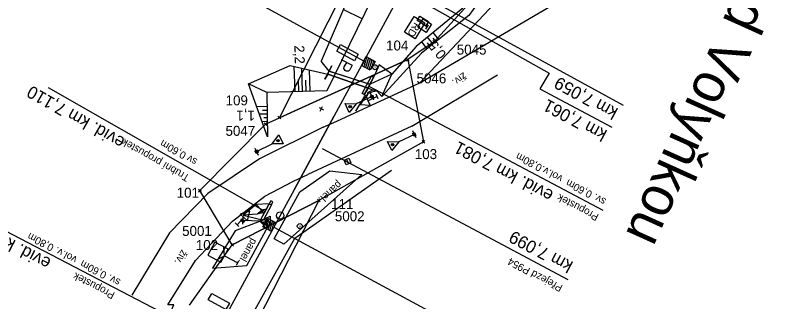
# Model space of a CAD drawing. Extents: x -795094 to -794639, y -1135368 to -1134681.
# Drawn here: x -794952.7 to -794797.7, y -1135065.2 to -1135007.8 of the extents above; entities that cross this region are included whole.
import ezdxf

# ---------------------------------------------------------------- set-up
doc = ezdxf.new("R2010")
doc.units = 0
for name, color, linetype in [('0381KM005-009P - Vrstva 1', 7, 'Continuous'), ('0381KM005-009P - Vrstva 12', 7, 'Continuous'), ('0381KM005-009P - Vrstva 13', 7, 'Continuous'), ('0381KM005-009P - Vrstva 16', 7, 'Continuous'), ('0381KM005-009P - Vrstva 17', 7, 'Continuous'), ('0381KM005-009P - Vrstva 19', 7, 'Continuous'), ('0381KM005-009P - Vrstva 2', 7, 'Continuous'), ('0381KM005-009P - Vrstva 23', 7, 'Continuous'), ('0381KM005-009P - Vrstva 25', 7, 'Continuous'), ('0381KM005-009P - Vrstva 28', 7, 'Continuous'), ('0381KM005-009P - Vrstva 3', 7, 'Continuous'), ('0381KM005-009P - Vrstva 33', 7, 'Continuous'), ('0381KM005-009P - Vrstva 4', 7, 'Continuous'), ('0381KM005-009P - Vrstva 43', 7, 'Continuous'), ('0381KM005-009P - Vrstva 48', 7, 'Continuous'), ('0381KM005-009P - Vrstva 49', 7, 'Continuous'), ('0381KM005-009P - Vrstva 51', 7, 'Continuous'), ('0381KM005-009P - Vrstva 7', 7, 'Continuous'), ('szdc - hran DP', 7, 'Continuous'), ('szdc - szdc_cislo', 7, 'Continuous'), ('szdc - szdc_krizek', 7, 'Continuous'), ('TZ - TZ_cislo', 7, 'Continuous'), ('TZ - TZ_krizek', 7, 'Continuous'), ('TZ - TZ_ostat', 7, 'Continuous')]:
    doc.layers.add(name, color=color, linetype=linetype)

msp = doc.modelspace()

# ---------------------------------------------------------------- linework, layer by layer
at = {"layer": '0381KM005-009P - Vrstva 1'}
for points in [[(-794874.77, -1135001.82), (-794875.27, -1135002.76), (-794882.94, -1135016.95), (-794888.88, -1135027.93)], [(-794888.88, -1135027.93), (-794896.92, -1135042.83), (-794900.95, -1135050.28), (-794913.19, -1135072.81), (-794931.08, -1135105.64), (-794935.69, -1135114.26)]]:
    msp.add_lwpolyline(points, dxfattribs=at)
at = {"layer": '0381KM005-009P - Vrstva 12'}
for p, q in [((-794881.46, -1135024.4), (-794881.59, -1135023.95)), ((-794881.14, -1135023.79), (-794881.13, -1135023.79)), ((-794872.92, -1135032.06), (-794872.91, -1135032.06)), ((-794872.5, -1135031.85), (-794872.5, -1135031.85)), ((-794907.35, -1135048.62), (-794907.35, -1135048.62)), ((-794907.6, -1135048.97), (-794907.58, -1135048.95)), ((-794907.09, -1135049.34), (-794907.1, -1135049.36)), ((-794906.84, -1135049.01), (-794906.84, -1135049.01))]:
    msp.add_line(p, q, dxfattribs=at)
for points in [[(-794881.59, -1135023.95), (-794881.14, -1135023.79), (-794880.98, -1135024.24), (-794881.46, -1135024.39), (-794881.59, -1135023.95), (-794881.59, -1135023.95), (-794881.13, -1135023.79), (-794880.98, -1135024.24), (-794880.98, -1135024.24)], [(-794880.98, -1135024.24), (-794881.46, -1135024.4), (-794881.46, -1135024.39)], [(-794873.17, -1135031.49), (-794872.8, -1135031.31), (-794872.5, -1135031.85), (-794872.92, -1135032.06), (-794873.17, -1135031.49), (-794873.17, -1135031.5), (-794872.8, -1135031.31), (-794872.5, -1135031.85), (-794872.91, -1135032.06), (-794873.17, -1135031.5)], [(-794904.34, -1135035.49), (-794904.78, -1135035.05), (-794904.46, -1135034.75), (-794904.04, -1135035.23), (-794904.34, -1135035.49)], [(-794907.6, -1135048.97), (-794907.35, -1135048.62), (-794906.84, -1135049.01), (-794907.09, -1135049.34), (-794907.6, -1135048.97)], [(-794907.58, -1135048.95), (-794907.35, -1135048.62), (-794906.84, -1135049.01), (-794907.1, -1135049.36), (-794907.58, -1135048.95)]]:
    msp.add_lwpolyline(points, dxfattribs=at)
at = {"layer": '0381KM005-009P - Vrstva 13'}
msp.add_line((-794884.56, -1135027.04), (-794882.71, -1135024.01), dxfattribs=at)
for points in [[(-794882.37, -1135024.01), (-794882.1, -1135023.18), (-794881.15, -1135022.72), (-794880.34, -1135022.96)], [(-794882.37, -1135024.01), (-794881.98, -1135023.4), (-794881.04, -1135023.04), (-794880.34, -1135022.96)]]:
    msp.add_lwpolyline(points, dxfattribs=at)
at = {"layer": '0381KM005-009P - Vrstva 16'}
for points in [[(-794898.94, -1135053.67), (-794900.91, -1135052.62), (-794895.75, -1135043.22), (-794889.78, -1135038.98), (-794883.31, -1135039.73)], [(-794906.39, -1135057.97), (-794902.12, -1135050.06), (-794903.85, -1135049.17), (-794908.68, -1135051.01), (-794913.25, -1135058.52)]]:
    msp.add_lwpolyline(points, close=True, dxfattribs=at)
at = {"layer": '0381KM005-009P - Vrstva 17'}
msp.add_lwpolyline([(-794906.48, -1135078.85), (-794910.34, -1135076.94), (-794896.76, -1135052.47), (-794877.42, -1135038.88)], dxfattribs=at)
at = {"layer": '0381KM005-009P - Vrstva 19'}
for p, q in [((-794889.88, -1135018.97), (-794881.68, -1135021.6)), ((-794881.72, -1135021.67), (-794889.88, -1135018.99)), ((-794882.1, -1135022.38), (-794890.17, -1135019.59)), ((-794890.16, -1135019.57), (-794882.1, -1135022.38)), ((-794880.99, -1135020.22), (-794880.96, -1135020.15)), ((-794902.71, -1135047.12), (-794946.12, -1135022.34)), ((-794881.93, -1135021.97), (-794835.06, -1135046.89)), ((-794901.41, -1135045.78), (-794901.14, -1135045.23)), ((-794903.29, -1135047.16), (-794904.32, -1135047.68)), ((-794916, -1135071.26), (-794961.47, -1135047.52))]:
    msp.add_line(p, q, dxfattribs=at)
for points in [[(-794890.17, -1135019.59), (-794890.74, -1135020.61), (-794889.35, -1135017.89), (-794889.88, -1135018.97)], [(-794890.17, -1135019.59), (-794890.16, -1135019.57), (-794889.88, -1135018.99), (-794889.88, -1135018.97)], [(-794881.43, -1135019.98), (-794880.96, -1135020.15), (-794881.68, -1135021.6), (-794881.72, -1135021.67), (-794882.1, -1135022.38), (-794882.1, -1135022.38), (-794882.86, -1135023.7)], [(-794903.57, -1135048.72), (-794902.85, -1135047.4), (-794902.85, -1135047.4), (-794902.44, -1135046.65), (-794902.44, -1135046.66), (-794901.89, -1135045.6)], [(-794901.14, -1135045.23), (-794901.54, -1135045.02), (-794901.89, -1135045.6)], [(-794903.11, -1135047.41), (-794904.32, -1135047.68), (-794903.41, -1135046.89)]]:
    msp.add_lwpolyline(points, dxfattribs=at)
for points in [[(-794881.43, -1135019.98), (-794880.99, -1135020.22), (-794882.86, -1135023.7), (-794883.29, -1135023.48)], [(-794903.13, -1135048.93), (-794903.57, -1135048.72), (-794901.89, -1135045.6), (-794901.41, -1135045.78)]]:
    msp.add_lwpolyline(points, close=True, dxfattribs=at)
msp.add_ellipse((-794903.26, -1135047.17), major_axis=(0.173, -0.304), ratio=0.062911, start_param=2.649673, end_param=6.913725, dxfattribs=at)
at = {"layer": '0381KM005-009P - Vrstva 2'}
msp.add_line((-794830.92, -1135025.88), (-794874.77, -1135001.82), dxfattribs=at)
at = {"layer": '0381KM005-009P - Vrstva 23'}
msp.add_lwpolyline([(-794874.82, -1135011.19), (-794872.86, -1135008.04), (-794870.71, -1135009.3), (-794872.68, -1135012.53)], close=True, dxfattribs=at)
at = {"layer": '0381KM005-009P - Vrstva 25'}
msp.add_lwpolyline([(-794870.01, -1135009), (-794870.52, -1135009.86), (-794872.24, -1135008.85), (-794871.74, -1135007.98), (-794870.01, -1135009)], dxfattribs=at)
at = {"layer": '0381KM005-009P - Vrstva 28'}
for p, q in [((-794880.68, -1135018.15), (-794880.73, -1135018.23)), ((-794902.92, -1135049.17), (-794902.97, -1135049.26))]:
    msp.add_line(p, q, dxfattribs=at)
for centre in [(-794880.7, -1135018.19), (-794902.95, -1135049.22)]:
    msp.add_circle(centre, 0.5, dxfattribs=at)
at = {"layer": '0381KM005-009P - Vrstva 3'}
for p, q in [((-794882.94, -1135016.95), (-794926.07, -1134993.29)), ((-794881.65, -1135018.78), (-794882.46, -1135016.07)), ((-794883.05, -1135018.03), (-794883.22, -1135017.47)), ((-794882.59, -1135018.28), (-794882.97, -1135017.01)), ((-794882.12, -1135018.53), (-794882.72, -1135016.54)), ((-794881.4, -1135018.32), (-794882, -1135016.33)), ((-794881.15, -1135017.85), (-794881.53, -1135016.58)), ((-794880.9, -1135017.38), (-794881.06, -1135016.83)), ((-794902.23, -1135048.45), (-794901.42, -1135051.16)), ((-794901.76, -1135048.7), (-794901.17, -1135050.69)), ((-794902.98, -1135049.84), (-794902.82, -1135050.4)), ((-794902.73, -1135049.38), (-794902.35, -1135050.65)), ((-794902.48, -1135048.91), (-794901.89, -1135050.9)), ((-794901.29, -1135048.95), (-794900.92, -1135050.23)), ((-794900.95, -1135050.28), (-794850.2, -1135077.72)), ((-794900.83, -1135049.21), (-794900.66, -1135049.76))]:
    msp.add_line(p, q, dxfattribs=at)
msp.add_lwpolyline([(-794875.27, -1135002.76), (-794845.8, -1135019.38), (-794847.67, -1135022.54), (-794833.28, -1135030.23)], dxfattribs=at)
for points in [[(-794883.41, -1135017.83), (-794882.46, -1135016.07), (-794880.7, -1135017.02), (-794881.65, -1135018.78)], [(-794900.47, -1135049.4), (-794901.42, -1135051.16), (-794903.18, -1135050.2), (-794902.23, -1135048.45)]]:
    msp.add_lwpolyline(points, close=True, dxfattribs=at)
at = {"layer": '0381KM005-009P - Vrstva 33'}
for p, q in [((-794870.35, -1135010.12), (-794871.19, -1135009.59)), ((-794870.08, -1135009.7), (-794870.61, -1135010.55))]:
    msp.add_line(p, q, dxfattribs=at)
for points in [[(-794869.39, -1135009.54), (-794870.45, -1135011.24), (-794872.15, -1135010.18), (-794871.09, -1135008.48), (-794869.39, -1135009.54)], [(-794887.47, -1135016.62), (-794885.26, -1135017.81)], [(-794886.85, -1135018.14), (-794886.35, -1135017.22)], [(-794885.26, -1135017.81), (-794885.76, -1135018.73)], [(-794885.76, -1135018.73), (-794886, -1135018.96), (-794886.46, -1135018.96), (-794886.66, -1135018.86), (-794886.92, -1135018.46), (-794886.85, -1135018.14)]]:
    msp.add_lwpolyline(points, dxfattribs=at)
for points in [[(-794884.07, -1135015.58), (-794884.78, -1135016.89), (-794888.32, -1135014.98), (-794887.61, -1135013.67)], [(-794909.87, -1135065.52), (-794910.59, -1135066.82), (-794914.13, -1135064.9), (-794913.41, -1135063.59)]]:
    msp.add_lwpolyline(points, close=True, dxfattribs=at)
at = {"layer": '0381KM005-009P - Vrstva 4'}
for p, q in [((-794880.96, -1135024.79), (-794881.61, -1135023.37)), ((-794885.44, -1135026.22), (-794885.9, -1135026.04)), ((-794896.92, -1135042.83), (-794888.88, -1135027.93)), ((-794872.48, -1135032.38), (-794873.14, -1135030.97)), ((-794900.36, -1135032.84), (-794899.9, -1135033)), ((-794904.79, -1135034.42), (-794904.09, -1135035.82)), ((-794891.29, -1135034.51), (-794842.11, -1135060.79)), ((-794876.96, -1135033.83), (-794877.42, -1135033.66)), ((-794907.18, -1135048.11), (-794907.23, -1135049.66)), ((-794902.53, -1135048.84), (-794902.2, -1135049.2))]:
    msp.add_line(p, q, dxfattribs=at)
for points in [[(-794881.29, -1135024.08), (-794884.45, -1135025.53), (-794885.86, -1135027.27), (-794886.7, -1135025.45), (-794884.45, -1135025.53)], [(-794872.81, -1135031.68), (-794875.96, -1135033.14), (-794877.36, -1135034.89), (-794878.21, -1135033.08), (-794875.96, -1135033.14)], [(-794904.44, -1135035.12), (-794901.33, -1135033.56), (-794899.98, -1135031.78), (-794899.08, -1135033.56), (-794901.33, -1135033.56)], [(-794907.2, -1135048.89), (-794903.73, -1135049), (-794901.69, -1135048.08), (-794901.75, -1135050.08), (-794903.73, -1135049)]]:
    msp.add_lwpolyline(points, dxfattribs=at)
for centre in [(-794885.67, -1135026.13), (-794900.13, -1135032.92), (-794877.19, -1135033.75), (-794902.37, -1135049.02)]:
    msp.add_circle(centre, 0.248, dxfattribs=at)
at = {"layer": '0381KM005-009P - Vrstva 43'}
msp.add_lwpolyline([(-794886.42, -1135036.65), (-794885.96, -1135036.44), (-794885.54, -1135037.35), (-794886.45, -1135037.77), (-794886.87, -1135036.86), (-794886.42, -1135036.65), (-794885.99, -1135037.56)], dxfattribs=at)
at = {"layer": '0381KM005-009P - Vrstva 48'}
for p, q in [((-794883.29, -1135008.47), (-794887.06, -1135006.62)), ((-794867.9, -1135012.61), (-794869.03, -1135011.2)), ((-794870.23, -1135014.49), (-794871.35, -1135013.1)), ((-794869.07, -1135013.55), (-794870.19, -1135012.15)), ((-794868.48, -1135013.08), (-794869.05, -1135012.38)), ((-794869.65, -1135014.02), (-794870.21, -1135013.32)), ((-794896.71, -1135023.1), (-794896.86, -1135018.05)), ((-794895.21, -1135023.06), (-794895.35, -1135018.4)), ((-794893.71, -1135023.01), (-794893.84, -1135018.74)), ((-794895.96, -1135023.08), (-794896.03, -1135020.65)), ((-794894.46, -1135023.03), (-794894.53, -1135020.8)), ((-794902.33, -1135026.11), (-794904.4, -1135026.14)), ((-794902.32, -1135026.86), (-794903.23, -1135026.88)), ((-794902.31, -1135027.61), (-794903.86, -1135027.63)), ((-794902.3, -1135028.36), (-794902.95, -1135028.37)), ((-794902.29, -1135029.11), (-794903.33, -1135029.13))]:
    msp.add_line(p, q, dxfattribs=at)
at = {"layer": '0381KM005-009P - Vrstva 49'}
for p, q in [((-794883.51, -1134998.27), (-794891.47, -1135016.98)), ((-794879, -1134999.7), (-794890.34, -1135022.91)), ((-794858.24, -1135002.66), (-794861.94, -1135007.83)), ((-794863.12, -1135006.37), (-794872.47, -1135014.02)), ((-794861.94, -1135007.83), (-794871.36, -1135015.4)), ((-794872.47, -1135014.02), (-794877.35, -1135019.62)), ((-794871.36, -1135015.4), (-794879.31, -1135024.09)), ((-794889.88, -1135018.97), (-794891.47, -1135016.98)), ((-794890.74, -1135020.61), (-794890.17, -1135019.59)), ((-794877.35, -1135019.62), (-794881.68, -1135021.6)), ((-794881.68, -1135021.6), (-794880.96, -1135020.15)), ((-794879.31, -1135024.09), (-794877.35, -1135019.62)), ((-794902.37, -1135023.27), (-794906.04, -1135021.56)), ((-794882.86, -1135023.7), (-794882.1, -1135022.38)), ((-794882.1, -1135022.38), (-794881.15, -1135022.72)), ((-794882.86, -1135023.7), (-794882.37, -1135024.01)), ((-794901.89, -1135045.6), (-794902.44, -1135046.66)), ((-794904.51, -1135045.76), (-794903.41, -1135046.89)), ((-794904.32, -1135047.68), (-794903.41, -1135046.89)), ((-794903.57, -1135048.72), (-794902.85, -1135047.4))]:
    msp.add_line(p, q, dxfattribs=at)
for points in [[(-794877.35, -1135019.62), (-794879.88, -1135017.7), (-794880.96, -1135020.15)], [(-794902.25, -1135032.15), (-794906.04, -1135021.56), (-794897.72, -1135017.85), (-794890.17, -1135019.59)], [(-794889.88, -1135018.97), (-794889.35, -1135017.89), (-794890.74, -1135020.61)], [(-794890.34, -1135022.91), (-794902.37, -1135023.27), (-794902.25, -1135032.15)], [(-794882.37, -1135024.01), (-794882.1, -1135023.18), (-794881.15, -1135022.72), (-794880.34, -1135022.96), (-794879.31, -1135024.09)], [(-794901.89, -1135045.6), (-794904.51, -1135045.76), (-794907.1, -1135047.88), (-794903.57, -1135048.72)], [(-794902.44, -1135046.66), (-794903.41, -1135046.89), (-794903.11, -1135047.41), (-794902.85, -1135047.4)], [(-794903.11, -1135047.41), (-794904.32, -1135047.68), (-794907.1, -1135047.88)]]:
    msp.add_lwpolyline(points, dxfattribs=at)
at = {"layer": '0381KM005-009P - Vrstva 51'}
for p, q in [((-794855.73, -1135004.24), (-794871.74, -1135021.34)), ((-794873.35, -1135030.02), (-794856.16, -1135019.75)), ((-794880.04, -1135024.54), (-794880.46, -1135023.63)), ((-794891.1, -1135030.2), (-794888.36, -1135029)), ((-794897.04, -1135041.09), (-794894.17, -1135039.74)), ((-794908.7, -1135049.45), (-794907.97, -1135050.14))]:
    msp.add_line(p, q, dxfattribs=at)
for points in [[(-794871.74, -1135021.34), (-794845.86, -1135006.13), (-794837.37, -1134998.39), (-794824.29, -1134983.58), (-794790.5, -1134931.65), (-794766.19, -1134894.56)], [(-794888.36, -1135029), (-794871.74, -1135021.34)], [(-794880.25, -1135024.08), (-794882.06, -1135024.92), (-794882.48, -1135024.01), (-794883.65, -1135025.65), (-794881.65, -1135025.83), (-794882.06, -1135024.92)], [(-794891.1, -1135030.2), (-794903.86, -1135036.61), (-794914.15, -1135043.55), (-794921.87, -1135051.41), (-794929.42, -1135063.92)], [(-794873.35, -1135030.02), (-794894.17, -1135039.74)], [(-794944.39, -1135111.84), (-794941.44, -1135105.51), (-794923.05, -1135070.46), (-794920.98, -1135065.89), (-794920.98, -1135065.89), (-794922.17, -1135065.85), (-794916.65, -1135057), (-794909.25, -1135049.07), (-794902.79, -1135044.1), (-794897.04, -1135041.09)], [(-794908.33, -1135049.8), (-794906.97, -1135048.33), (-794906.24, -1135049.02), (-794905.78, -1135047.05), (-794907.7, -1135047.65), (-794906.97, -1135048.33)]]:
    msp.add_lwpolyline(points, dxfattribs=at)
at = {"layer": '0381KM005-009P - Vrstva 7'}
for p, q in [((-794891.9, -1135026.31), (-794891.02, -1135026.78)), ((-794891.7, -1135026.99), (-794891.22, -1135026.11)), ((-794895.73, -1135050.04), (-794895.78, -1135050.13)), ((-794910.84, -1135056.03), (-794908.2, -1135057.46)), ((-794908.44, -1135057.9), (-794907.97, -1135057.02))]:
    msp.add_line(p, q, dxfattribs=at)
for points in [[(-794910.84, -1135056.03), (-794910.12, -1135054.71), (-794912.76, -1135053.28), (-794914.19, -1135055.91), (-794911.56, -1135057.34), (-794910.84, -1135056.03)], [(-794912.44, -1135056.87), (-794910.84, -1135056.03), (-794911, -1135054.23)]]:
    msp.add_lwpolyline(points, dxfattribs=at)
for centre, radius in [((-794899.69, -1135047.96), 0.75), ((-794895.76, -1135050.08), 0.5)]:
    msp.add_circle(centre, radius, dxfattribs=at)
at = {"layer": 'szdc - hran DP'}
for p, q in [((-794899.86, -1135028.32), (-794880.53, -1134990.11)), ((-794854.54, -1134997.31), (-794868.85, -1135013.13)), ((-794868.85, -1135013.13), (-794874.12, -1135016.68)), ((-794874.12, -1135016.68), (-794899.86, -1135028.32)), ((-794909.29, -1135053.85), (-794891.95, -1135044.96)), ((-794891.95, -1135044.96), (-794908.62, -1135077.55)), ((-794917.84, -1135065.96), (-794909.29, -1135053.85))]:
    msp.add_line(p, q, dxfattribs=at)
at = {"layer": 'szdc - szdc_krizek'}
for p, q in [((-794868.58, -1135013.4), (-794869.12, -1135012.86)), ((-794869.12, -1135013.4), (-794868.58, -1135012.86)), ((-794873.85, -1135016.95), (-794874.39, -1135016.42)), ((-794874.39, -1135016.95), (-794873.85, -1135016.42)), ((-794899.59, -1135028.58), (-794900.13, -1135028.05)), ((-794900.13, -1135028.58), (-794899.59, -1135028.05)), ((-794891.69, -1135045.23), (-794892.22, -1135044.7)), ((-794892.22, -1135045.23), (-794891.69, -1135044.7)), ((-794909.03, -1135054.11), (-794909.56, -1135053.58)), ((-794909.56, -1135054.11), (-794909.03, -1135053.58))]:
    msp.add_line(p, q, dxfattribs=at)
at = {"layer": 'TZ - TZ_krizek'}
for p, q in [((-794873.85, -1135016.95), (-794874.39, -1135016.42)), ((-794874.39, -1135016.95), (-794873.85, -1135016.42)), ((-794902.38, -1135029.9), (-794902.91, -1135029.36)), ((-794902.91, -1135029.9), (-794902.38, -1135029.36)), ((-794870.73, -1135033.46), (-794871.27, -1135032.93)), ((-794871.27, -1135033.46), (-794870.73, -1135032.93)), ((-794915.52, -1135043.23), (-794916.06, -1135042.7)), ((-794916.06, -1135043.23), (-794915.52, -1135042.7)), ((-794891.69, -1135045.23), (-794892.22, -1135044.7)), ((-794892.22, -1135045.23), (-794891.69, -1135044.7)), ((-794909.03, -1135054.11), (-794909.56, -1135053.58)), ((-794909.56, -1135054.11), (-794909.03, -1135053.58))]:
    msp.add_line(p, q, dxfattribs=at)
at = {"layer": 'TZ - TZ_ostat'}
for p, q in [((-794902.64, -1135029.63), (-794874.12, -1135016.68)), ((-794874.12, -1135016.68), (-794871, -1135033.19)), ((-794915.79, -1135042.96), (-794902.64, -1135029.63)), ((-794909.29, -1135053.85), (-794915.79, -1135042.96))]:
    msp.add_line(p, q, dxfattribs=at)
msp.add_lwpolyline([(-794871, -1135033.19), (-794891.95, -1135044.96), (-794909.29, -1135053.85)], dxfattribs=at)

# ---------------------------------------------------------------- texts
at = {"layer": '0381KM005-009P - Vrstva 16'}
for rotation, p in [(221.741, (-794888.11, -1135040.9)), (240.3758, (-794905.43, -1135052.38))]:
    msp.add_text('panel.', height=1.5, rotation=rotation, dxfattribs=at).set_placement(p)
at = {"layer": '0381KM005-009P - Vrstva 19'}
for s, height, rotation, p in [('evid. km 7,110', 2.5, 150.2746, (-794930.6, -1135032.56)), ('Trubní propustek', 1.5, 150.2746, (-794917.7, -1135039.96)), ('sv 0,60m', 1.5, 150.2746, (-794916.14, -1135036.71)), ('evid. km 7,081', 2.5, 152.0063, (-794844.78, -1135043.17)), ('sv. 0,60m  vol.v.0,80m', 1.5, 152.0063, (-794834.29, -1135044.69)), ('Propustek', 1.5, 152.0063, (-794835.75, -1135047.8)), ('evid. km 7,140', 2.5, 152.4236, (-794945.4, -1135056.76)), ('sv. 0,60m  vol.v. 0,80m', 1.5, 152.4236, (-794931.54, -1135060.88)), ('Propustek', 1.5, 152.4236, (-794932.67, -1135063.48))]:
    msp.add_text(s, height=height, rotation=rotation, dxfattribs=at).set_placement(p)
at = {"layer": '0381KM005-009P - Vrstva 2'}
msp.add_text('km 7,059', height=2.5, rotation=151.2416, dxfattribs=at).set_placement((-794831.83, -1135026.6))
at = {"layer": '0381KM005-009P - Vrstva 23'}
for s, height, rotation, p in [('žst. Strunkovice nad Volyňkou', 8, 245.663, (-794771.54, -1134921.22)), ('RD', 1.5, 238.5762, (-794872.79, -1135009.08))]:
    msp.add_text(s, height=height, rotation=rotation, dxfattribs=at).set_placement(p)
at = {"layer": '0381KM005-009P - Vrstva 3'}
msp.add_text('km 7,061', height=2.5, rotation=151.8622, dxfattribs=at).set_placement((-794834.01, -1135030.99))
at = {"layer": '0381KM005-009P - Vrstva 4'}
for s, height, p in [('km 7,099', 2.5, (-794840.84, -1135057.37)), ('Přejezd P954', 1.5, (-794842.99, -1135062.04))]:
    msp.add_text(s, height=height, rotation=151.8782, dxfattribs=at).set_placement(p)
at = {"layer": '0381KM005-009P - Vrstva 48'}
for s, rotation, p in [('0,5', 128.7976, (-794866.31, -1135015.57)), ('2,2', 271.7048, (-794896.86, -1135013.83)), ('1,1', 180.7873, (-794904.76, -1135026.88))]:
    msp.add_text(s, height=2, rotation=rotation, dxfattribs=at).set_placement(p)
at = {"layer": '0381KM005-009P - Vrstva 51'}
for rotation, p in [(215.8489, (-794862.99, -1135019.13)), (238.8782, (-794919.38, -1135054.69))]:
    msp.add_text('živ.', height=1.5, rotation=rotation, dxfattribs=at).set_placement(p)
at = {"layer": 'szdc - szdc_cislo'}
for s, p in [('5045', (-794864.33, -1135015.67)), ('5046', (-794872.38, -1135021.43)), ('5047', (-794910.64, -1135031.96)), ('5002', (-794888.74, -1135049.1)), ('5001', (-794919.33, -1135052.04))]:
    msp.add_text(s, height=2, dxfattribs=at).set_placement(p)
at = {"layer": 'TZ - TZ_cislo'}
for s, p in [('104', (-794878.49, -1135014.84)), ('109', (-794910.62, -1135025.85)), ('103', (-794872.73, -1135036.63)), ('101', (-794920.42, -1135044.37)), ('111', (-794889.49, -1135046.63)), ('102', (-794916.59, -1135054.87))]:
    msp.add_text(s, height=2, dxfattribs=at).set_placement(p)

doc.saveas('drawing.dxf')
